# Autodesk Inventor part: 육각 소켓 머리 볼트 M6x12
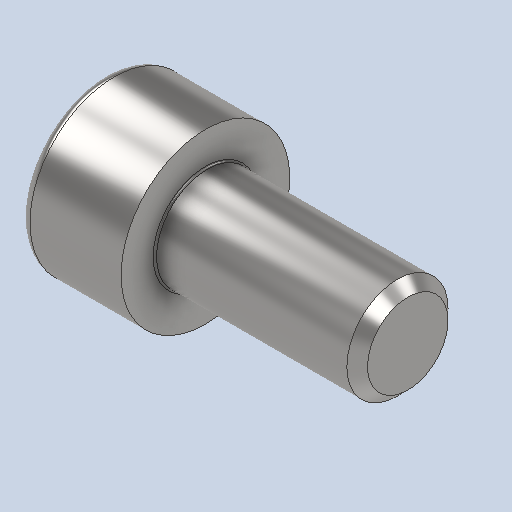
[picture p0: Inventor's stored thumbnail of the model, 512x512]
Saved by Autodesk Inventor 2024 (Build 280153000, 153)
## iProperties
Created: 2024-07
Part Number: 육각 소켓 머리 볼트 M6x12
Material: 강철, 연강
Description: 6각머리 태핑 나사
Document SubType Name: Modeling
Designer: com
Density: 7.85 g/cm^3
Appearance: 기본값
Author: jhkim
Sending System: Autodesk Inventor 2025
Preprocessor: ST-DEVELOPER v20
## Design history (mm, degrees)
feature "Solid1"
node "솔리드1"
